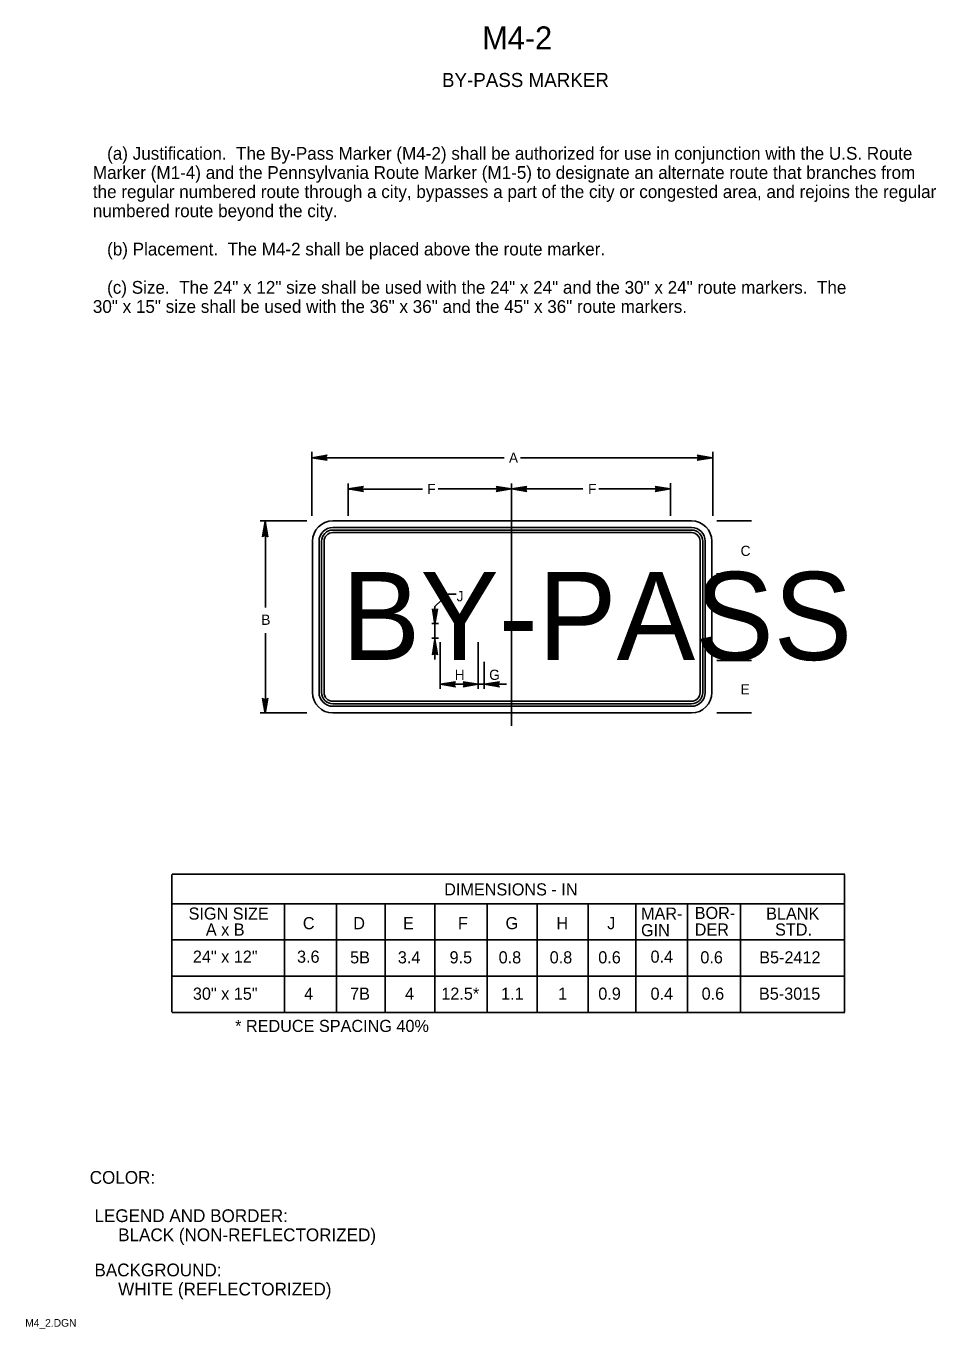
# Model space of a CAD drawing. Extents: x 0.013 to 0.191, y 0.004 to 0.259.
import ezdxf

# ---------------------------------------------------------------- set-up
doc = ezdxf.new("R2010")
doc.units = 0
for name, color, linetype in [('1', 7, 'Continuous'), ('2', 7, 'Continuous'), ('3', 7, 'Continuous')]:
    doc.layers.add(name, color=color, linetype=linetype)

# ---------------------------------------------------------------- blocks, each defined once
blk = doc.blocks.new('RARROW')
at = {"layer": '3'}
for p, q in [((-2.156, 0.285), (-2.2665, 0.384625)), ((-2.2665, 0.384625), (0, 0)), ((0, 0), (-2.2665, -0.379125)), ((-2.156, 0.285), (-2.075625, 0.12075)), ((0, 0), (-2.156, 0.285)), ((-2.14975, -0.2705), (0, 0)), ((-2.075625, 0.12075), (0, 0)), ((0, 0), (-2.074, -0.108)), ((-2.2665, -0.379125), (-2.14975, -0.2705)), ((-2.074, -0.108), (-2.14975, -0.2705))]:
    blk.add_line(p, q, dxfattribs=at)

msp = doc.modelspace()

# ---------------------------------------------------------------- linework, layer by layer
at = {"layer": '3'}
for p, q in [((0.06862, 0.16325), (0.06862, 0.17575)), ((0.10634, 0.17463), (0.06871, 0.17463)), ((0.1095, 0.17463), (0.14717, 0.17463)), ((0.14717, 0.16325), (0.14717, 0.17575)), ((0.07575, 0.16322), (0.07575, 0.1696)), ((0.09034, 0.16848), (0.07584, 0.16848)), ((0.09337, 0.1685), (0.10775, 0.1685)), ((0.10775, 0.16423), (0.10775, 0.1696)), ((0.12175, 0.1685), (0.10775, 0.1685)), ((0.12487, 0.1685), (0.13892, 0.1685)), ((0.13892, 0.16325), (0.13892, 0.16962)), ((0.10775, 0.12212), (0.10775, 0.165)), ((0.06767, 0.16225), (0.05854, 0.16225)), ((0.05954, 0.14525), (0.05954, 0.16225)), ((0.07275, 0.16225), (0.143, 0.16225)), ((0.07275, 0.16095), (0.143, 0.16095)), ((0.148, 0.16225), (0.15475, 0.16225)), ((0.07275, 0.16045), (0.143, 0.16045)), ((0.07275, 0.15995), (0.143, 0.15995)), ((0.06875, 0.12862), (0.06875, 0.15825)), ((0.07005, 0.12862), (0.07005, 0.15825)), ((0.07055, 0.12862), (0.07055, 0.15825)), ((0.07105, 0.12862), (0.07105, 0.15825)), ((0.1447, 0.15825), (0.1447, 0.12862)), ((0.1452, 0.15825), (0.1452, 0.12862)), ((0.1457, 0.15825), (0.1457, 0.12862)), ((0.147, 0.15825), (0.147, 0.12862)), ((0.14788, 0.15188), (0.15475, 0.15188)), ((0.09275, 0.1455), (0.09525, 0.14788)), ((0.09275, 0.1455), (0.09275, 0.13512)), ((0.09688, 0.14788), (0.09525, 0.14788)), ((0.09342, 0.14212), (0.09217, 0.14212)), ((0.05954, 0.14025), (0.05954, 0.12462)), ((0.09342, 0.13925), (0.09217, 0.13925)), ((0.09375, 0.1385), (0.09375, 0.12933)), ((0.10125, 0.1385), (0.10125, 0.12933)), ((0.10242, 0.13462), (0.10242, 0.12933)), ((0.148, 0.13487), (0.15475, 0.13487)), ((0.10125, 0.13023), (0.09375, 0.13023)), ((0.10242, 0.13023), (0.10125, 0.13023)), ((0.10675, 0.13023), (0.10242, 0.13023)), ((0.143, 0.12693), (0.07275, 0.12693)), ((0.143, 0.12643), (0.07275, 0.12643)), ((0.143, 0.12593), (0.07275, 0.12593)), ((0.06767, 0.12462), (0.05854, 0.12462)), ((0.143, 0.12462), (0.07275, 0.12462)), ((0.148, 0.12462), (0.15475, 0.12462)), ((0.04125, 0.093), (0.04125, 0.066)), ((0.04129, 0.09304), (0.17304, 0.09304)), ((0.173, 0.093), (0.173, 0.066)), ((0.17304, 0.08725), (0.04129, 0.08725)), ((0.0633, 0.08725), (0.0633, 0.06595)), ((0.0735, 0.08725), (0.0735, 0.066)), ((0.083, 0.08725), (0.083, 0.066)), ((0.09275, 0.08725), (0.09275, 0.066)), ((0.103, 0.08725), (0.103, 0.066)), ((0.11275, 0.08725), (0.11275, 0.066)), ((0.12275, 0.08725), (0.12275, 0.066)), ((0.13211, 0.08725), (0.13211, 0.06595)), ((0.14225, 0.08725), (0.14225, 0.06595)), ((0.1526, 0.08725), (0.1526, 0.06595)), ((0.17304, 0.08015), (0.04129, 0.08015)), ((0.17304, 0.07305), (0.04129, 0.07305)), ((0.17304, 0.06595), (0.04129, 0.06595))]:
    msp.add_line(p, q, dxfattribs=at)
for centre, radius, start, end in [((0.07275, 0.15825), 0.004, 90, 180), ((0.07275, 0.15825), 0.0027, 90, 180), ((0.143, 0.15825), 0.004, 0, 90), ((0.143, 0.15825), 0.0027, 0, 90), ((0.07275, 0.15825), 0.0022, 90, 180), ((0.07275, 0.15825), 0.0017, 90, 180), ((0.143, 0.15825), 0.0022, 0, 90), ((0.143, 0.15825), 0.0017, 0, 90), ((0.07275, 0.12862), 0.004, 180, 270), ((0.07275, 0.12862), 0.0027, 180, 270), ((0.07275, 0.12862), 0.0022, 180, 270), ((0.07275, 0.12862), 0.0017, 180, 270), ((0.143, 0.12862), 0.004, 270, 0), ((0.143, 0.12862), 0.0027, 270, 0), ((0.143, 0.12862), 0.0017, 270, 0), ((0.143, 0.12862), 0.0022, 270, 0)]:
    msp.add_arc(centre, radius, start, end, dxfattribs=at)

# ---------------------------------------------------------------- block references
at = {"layer": '3', "xscale": 0.0013236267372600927, "yscale": 0.001309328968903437}
for p, rotation in [((0.06863, 0.17463), 180), ((0.07575, 0.1685), 180), ((0.10775, 0.1685), 180), ((0.0595, 0.16212), 90), ((0.09275, 0.142), -90.00000000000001), ((0.09275, 0.139), 90), ((0.09375, 0.13023), 180), ((0.10238, 0.13023), 180), ((0.0595, 0.1245), -90)]:
    msp.add_blockref('RARROW', p, dxfattribs=dict(at, rotation=rotation))
for p in [(0.14713, 0.17463), (0.10775, 0.1685), (0.13887, 0.1685), (0.10125, 0.13023)]:
    msp.add_blockref('RARROW', p, dxfattribs=at)

# ---------------------------------------------------------------- texts
at = {"layer": '1'}
for s, height, p in [('M4-2', 0.0045, (0.102, 0.25462)), ('BY-PASS MARKER', 0.0027503, (0.09413, 0.24725)), ('COLOR:', 0.0025, (0.02513, 0.03238)), (' LEGEND AND BORDER:', 0.0024998, (0.02513, 0.02488)), ('      BLACK (NON-REFLECTORIZED)', 0.0024998, (0.02513, 0.02113)), (' BACKGROUND:', 0.0024998, (0.02513, 0.01425)), ('      WHITE (REFLECTORIZED)', 0.0024998, (0.02513, 0.0105)), ('M4_2.DGN', 0.0015, (0.0125, 0.00438))]:
    msp.add_text(s, height=height, dxfattribs=at).set_placement(p)
at = {"layer": '2'}
for s, height, p in [('   (a) Justification.  The By-Pass Marker (M4-2) shall be authorized for use in conjunction with the U.S. Route ', 0.00249975, (0.02575, 0.233)), ('Marker (M1-4) and the Pennsylvania Route Marker (M1-5) to designate an alternate route that branches from ', 0.00249975, (0.02575, 0.22925)), ('the regular numbered route through a city, bypasses a part of the city or congested area, and rejoins the regular ', 0.00249975, (0.02575, 0.2255)), ('numbered route beyond the city.', 0.0024998, (0.02575, 0.22175)), ('   (b) Placement.  The M4-2 shall be placed above the route marker.', 0.0024998, (0.02575, 0.21425)), ('   (c) Size.  The 24" x 12" size shall be used with the 24" x 24" and the 30" x 24" route markers.  The  ', 0.00249975, (0.02575, 0.20675)), ('30" x 15" size shall be used with the 36" x 36" and the 45" x 36" route markers.', 0.0024998, (0.02575, 0.203))]:
    msp.add_text(s, height=height, dxfattribs=at).set_placement(p)
at = {"layer": '3'}
for s, height, p in [('A', 0.002, (0.10725, 0.17363)), ('F', 0.002, (0.09125, 0.1675)), ('F', 0.002, (0.12275, 0.1675)), ('C', 0.002, (0.15263, 0.15538)), ('BY-PASS', 0.01725, (0.0745, 0.135)), ('J', 0.002, (0.097, 0.1465)), ('B', 0.002, (0.05875, 0.14188)), ('D', 0.002, (0.153, 0.14238)), ('H', 0.002, (0.09663, 0.1311)), ('G', 0.002, (0.10338, 0.1311)), ('E', 0.002, (0.15263, 0.12825)), ('DIMENSIONS - IN', 0.0023752, (0.09457, 0.08887)), ('SIGN SIZE', 0.002375, (0.0445, 0.08413)), ('C', 0.00238, (0.06688, 0.08225)), ('D', 0.00238, (0.07675, 0.08225)), ('E', 0.00238, (0.0865, 0.08225)), ('F', 0.00238, (0.09725, 0.08225)), ('G', 0.00238, (0.10658, 0.08225)), ('H', 0.00238, (0.11654, 0.08225)), ('J', 0.00238, (0.1265, 0.08225)), ('MAR-', 0.002375, (0.13312, 0.08413)), ('BOR-', 0.002375, (0.14363, 0.08425)), ('BLANK', 0.002375, (0.15763, 0.08413)), ('A x B', 0.002375, (0.04788, 0.081)), ('GIN', 0.002375, (0.13312, 0.08088)), ('DER', 0.002375, (0.14363, 0.081)), ('STD.', 0.002375, (0.15938, 0.081)), ('24" x 12"', 0.002375, (0.04534, 0.07569)), ('3.6', 0.002375, (0.06574, 0.07569)), ('5B', 0.002375, (0.07614, 0.07556)), ('3.4', 0.002375, (0.08548, 0.07556)), ('9.5', 0.002375, (0.09562, 0.07556)), ('0.8', 0.002375, (0.10523, 0.07556)), ('0.8', 0.002375, (0.11523, 0.07556)), ('0.6', 0.002375, (0.12474, 0.07556)), ('0.4', 0.002375, (0.13498, 0.07569)), ('0.6', 0.002375, (0.14474, 0.07556)), ('B5-2412', 0.002375, (0.15627, 0.07556)), ('30" x 15"', 0.002375, (0.04534, 0.06844)), ('4', 0.00238, (0.06714, 0.06844)), ('7B', 0.002375, (0.07614, 0.06844)), ('4', 0.00238, (0.08689, 0.06844)), ('12.5*', 0.002375, (0.094, 0.06844)), ('1.1', 0.002375, (0.10571, 0.06844)), ('1', 0.00238, (0.11689, 0.06844)), ('0.9', 0.002375, (0.12475, 0.06844)), ('0.4', 0.002375, (0.13498, 0.06844)), ('0.6', 0.002375, (0.14499, 0.06844)), ('B5-3015', 0.002375, (0.15622, 0.06844)), ('* REDUCE SPACING 40%', 0.0023752, (0.05362, 0.06212))]:
    msp.add_text(s, height=height, dxfattribs=at).set_placement(p)

doc.saveas('drawing.dxf')
